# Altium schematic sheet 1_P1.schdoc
size 358 x 218 mm; Symbol: Sheet-Symbol_A4; Device: Sheet-Symbol_A4; @Project Name: 无人机遥控器; @Page Count: 1; @Update Date: 2025-06-11; @Create Date: 2025-01-15; @Schematic Name: Schematic1; @Page No: 1; @Page Name: P1; @Board Name: Board1; Company: 嘉立创EDA; Version: V1.0; Page Size: A4; Convert to PCB: yes; Add into BOM: yes; @Create Time: 08:23:44; @Update Time: 22:29:00; Width: 1377.9527559055118; Height: 825; Region Start: 1; X Region Count: 6; Y Region Count: 4; Blade Width: 10; Title Block Position: 3
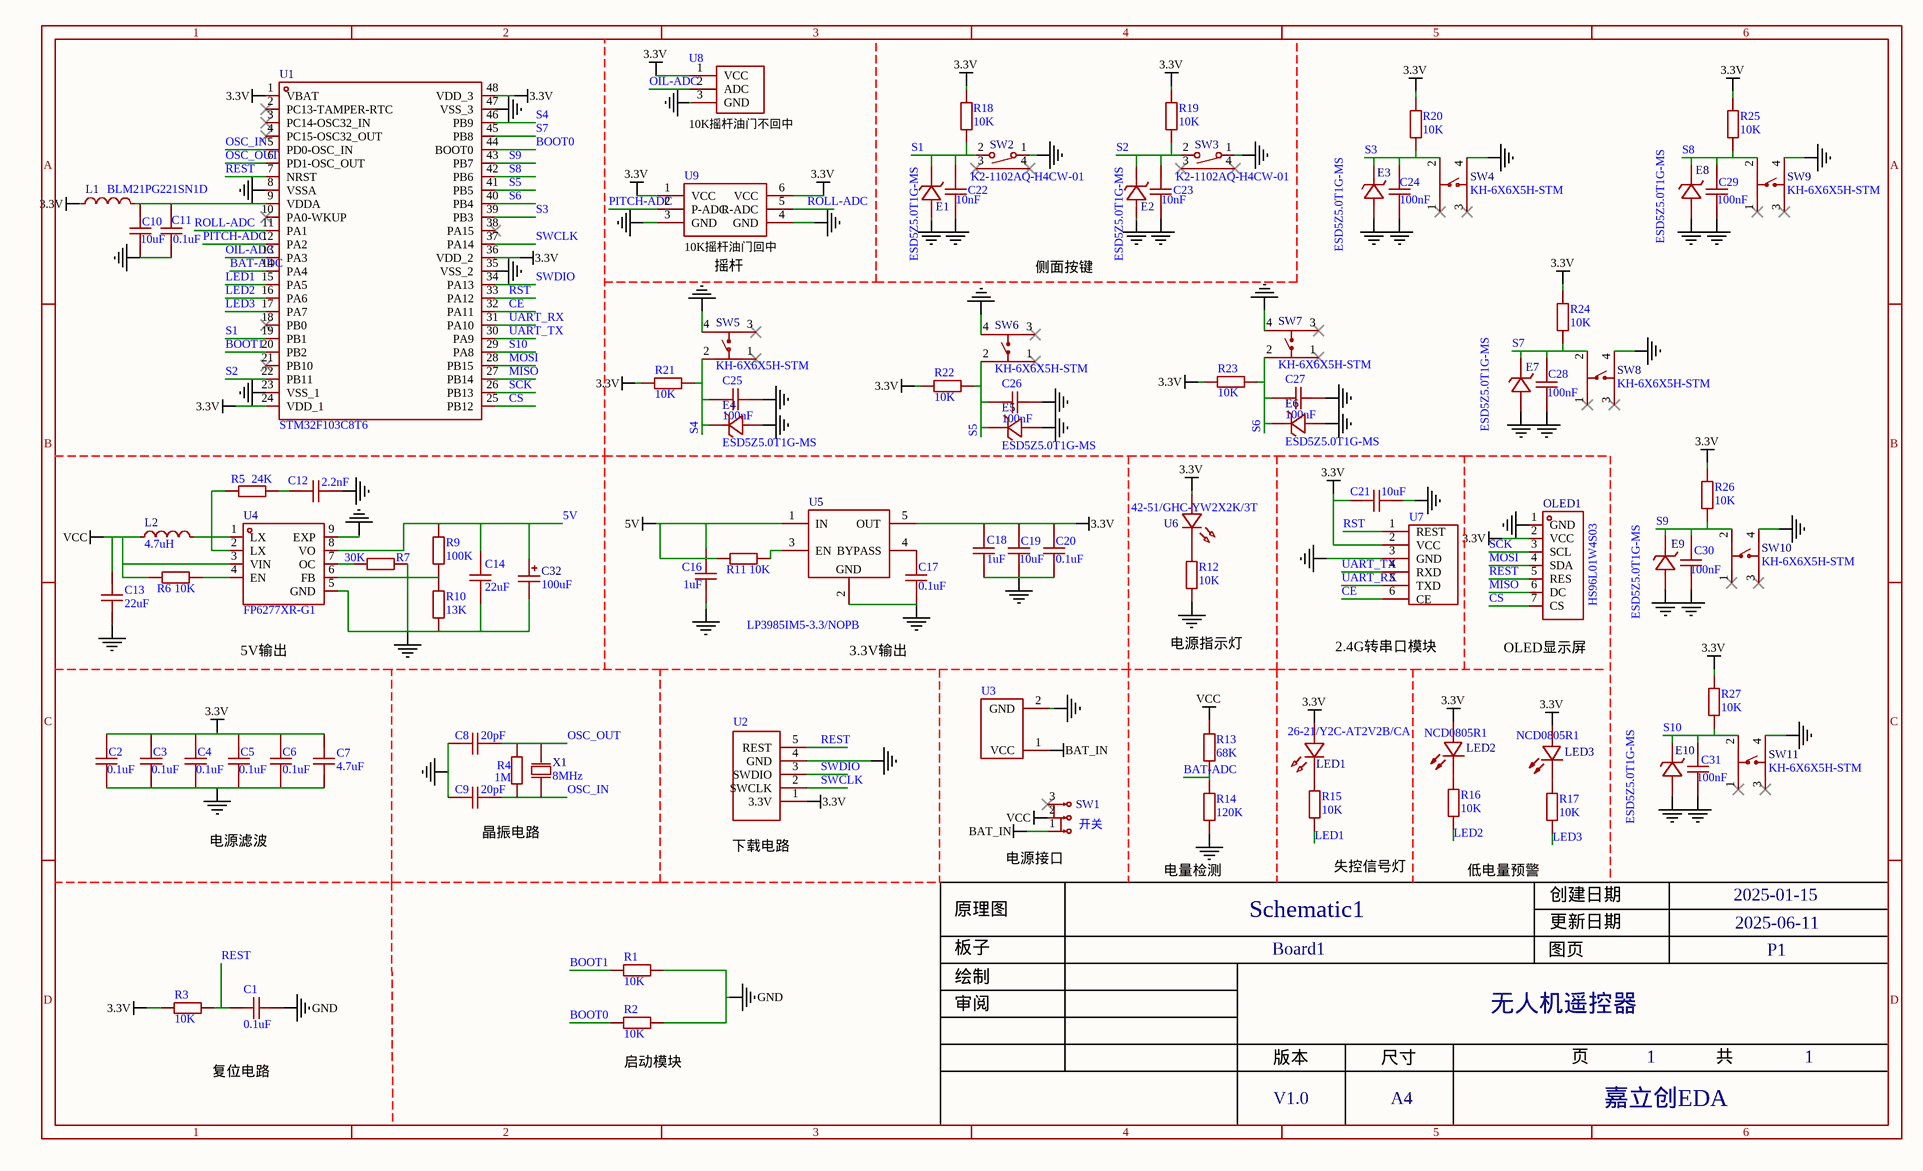
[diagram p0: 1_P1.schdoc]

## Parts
C1  0.1uF  [C0603]
C2  0.1uF  [C0603]
C3  0.1uF  [C0603]
C4  0.1uF  [C0603]
C5  0.1uF  [C0603]
C6  0.1uF  [C0603]
C7  4.7uF  [C0603]
C8  20pF  [C0603]
C9  20pF  [C0603]
C10  10uF  [C0603]
C11  0.1uF  [C0603]
C12  2.2nF  [C0603]
C13  22uF  [C0603]
C14  22uF  [C0603]
C16  1uF  [C0603]
C17  0.1uF  [C0603]
C18  1uF  [C0603]
C19  10uF  [C0603]
C20  0.1uF  [C0603]
C21  10uF  [C0603]
C22  10nF  [C0603]
C23  10nF  [C0603]
C24  100nF  [C0603]
C25  100nF  [C0603]
C26  100nF  [C0603]
C27  100nF  [C0603]
C28  100nF  [C0603]
C29  100nF  [C0603]
C30  100nF  [C0603]
C31  100nF  [C0603]
C32  100uF  [CASE-D_7343]
E1  ESD5Z5.0T1G-MS  [SOD-523_L1.2-W0.8-LS1.6-RD]
E2  ESD5Z5.0T1G-MS  [SOD-523_L1.2-W0.8-LS1.6-RD]
E3  ESD5Z5.0T1G-MS  [SOD-523_L1.2-W0.8-LS1.6-RD]
E4  ESD5Z5.0T1G-MS  [SOD-523_L1.2-W0.8-LS1.6-RD]
E5  ESD5Z5.0T1G-MS  [SOD-523_L1.2-W0.8-LS1.6-RD]
E6  ESD5Z5.0T1G-MS  [SOD-523_L1.2-W0.8-LS1.6-RD]
E7  ESD5Z5.0T1G-MS  [SOD-523_L1.2-W0.8-LS1.6-RD]
E8  ESD5Z5.0T1G-MS  [SOD-523_L1.2-W0.8-LS1.6-RD]
E9  ESD5Z5.0T1G-MS  [SOD-523_L1.2-W0.8-LS1.6-RD]
E10  ESD5Z5.0T1G-MS  [SOD-523_L1.2-W0.8-LS1.6-RD]
L1  BLM21PG221SN1D  [L0805]
L2  4.7uH  [L0603]
LED1  26-21/Y2C-AT2V2B/CA  [LED1206-RD]
LED2  NCD0805R1  [LED0805-R-RD]
LED3  NCD0805R1  [LED0805-R-RD]
OLED1  HS96L01W4S03  [OLED-TH_HS96L01W4S03]
R1  10K  [R0603]
R2  10K  [R0603]
R3  10K  [R0603]
R4  1M  [R0603]
R5  24K  [R0603]
R6  10K  [R0603]
R7  30K  [R0603]
R9  100K  [R0603]
R10  13K  [R0603]
R11  10K  [R0603]
R12  10K  [R0603]
R13  68K  [R0603]
R14  120K  [R0603]
R15  10K  [R0603]
R16  10K  [R0603]
R17  10K  [R0603]
R18  10K  [R0603]
R19  10K  [R0603]
R20  10K  [R0603]
R21  10K  [R0603]
R22  10K  [R0603]
R23  10K  [R0603]
R24  10K  [R0603]
R25  10K  [R0603]
R26  10K  [R0603]
R27  10K  [R0603]
SW1  开关  [SW-TH_SS-12D01-GX]
SW2  K2-1102AQ-H4CW-01  [SW-TH_K2-1102BQ-G4CW-01]
SW3  K2-1102AQ-H4CW-01  [SW-TH_K2-1102BQ-G4CW-01]
SW4  KH-6X6X5H-STM  [SW-SMD_4P-L6.0-W6.0-P4.50-LS9.0-2]
SW5  KH-6X6X5H-STM  [SW-SMD_4P-L6.0-W6.0-P4.50-LS9.0-2]
SW6  KH-6X6X5H-STM  [SW-SMD_4P-L6.0-W6.0-P4.50-LS9.0-2]
SW7  KH-6X6X5H-STM  [SW-SMD_4P-L6.0-W6.0-P4.50-LS9.0-2]
SW8  KH-6X6X5H-STM  [SW-SMD_4P-L6.0-W6.0-P4.50-LS9.0-2]
SW9  KH-6X6X5H-STM  [SW-SMD_4P-L6.0-W6.0-P4.50-LS9.0-2]
SW10  KH-6X6X5H-STM  [SW-SMD_4P-L6.0-W6.0-P4.50-LS9.0-2]
SW11  KH-6X6X5H-STM  [SW-SMD_4P-L6.0-W6.0-P4.50-LS9.0-2]
U1  STM32F103C8T6  [LQFP-48_L7.0-W7.0-P0.50-LS9.0-BL]
U2  (no value)  [stm32f103swd下载口]
U3  (no value)  [电源插座]
U4  FP6277XR-G1  [SOP-8_L4.9-W3.9-P1.27-LS6.0-BL-EP]
U5  LP3985IM5-3.3/NOPB  [SOT-23-5_L3.0-W1.7-P0.95-LS2.8-BR]
U6  42-51/GHC-YW2X2K/3T  [LED-SMD_L1.6-W0.8-FD_GREEN-1]
U7  (no value)  [2.4G转串口]
U8  (no value)  [10K摇杆油门不回中]
U9  (no value)  [10K摇杆油门回中]
X1  8MHz  [OSC-TH_L10.0-W4.5-P5.00]

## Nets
3.3V: C2.2 C3.2 C4.2 C5.2 C6.2 C7.2 C18.2 C19.2 C20.2 C21.1 L1.1 LED1.2(A) LED2.1(+) LED3.1(+) OLED1.2(VCC) R3.1 R18.2 R19.2 R20.2 R21.2 R22.2 R23.2 R24.2 R25.2 R26.2 R27.2 U1.1(VBAT) U1.24(VDD_1) U1.36(VDD_2) U1.48(VDD_3) U2.1(3.3V) U5.5(OUT) U6.1(A) U7.2(VCC) U8.1(VCC) U9.1(VCC) U9.6(VCC)
5V: C14.2 C16.2 C32.1 R9.2 R11.1 U4.8(VO) U5.1(IN)
BAT_IN: SW1.1 U3.1(VCC)
GND: C1.2 C2.1 C3.1 C4.1 C5.1 C6.1 C7.1 C8.1 C9.1 C10.1 C11.1 C12.2 C13.1 C14.1 C16.1 C17.1 C18.1 C19.1 C20.1 C21.2 C22.1 C23.1 C24.1 C25.1 C26.1 C27.1 C28.1 C29.1 C30.1 C31.1 C32.2 E1.2(A) E2.2(A) E3.2(A) E4.2(A) E5.2(A) E6.2(A) E7.2(A) E8.2(A) E9.2(A) E10.2(A) OLED1.1(GND) R1.2 R2.2 R7.2 R10.1 R12.2 R14.1 SW2.1 SW3.1 SW4.4 SW5.4 SW6.4 SW7.4 SW8.4 SW9.4 SW10.4 SW11.4 U1.8(VSSA) U1.23(VSS_1) U1.35(VSS_2) U1.47(VSS_3) U2.4(GND) U3.2(GND) U4.5(GND) U4.9(EXP) U5.2(GND) U7.3(GND) U8.3(GND) U9.3(GND) U9.4(GND)
VCC: C13.2 L2.1 R6.1 R13.2 SW1.2 U4.3(VIN)
BAT-ADC: R13.1 R14.2 U1.14(PA4)
BOOT0: R2.1 U1.44(BOOT0)
BOOT1: R1.1 U1.20(PB2)
CE: U1.32(PA11) U7.6(CE)
CS: OLED1.7(CS) U1.25(PB12)
LED1: R15.1 U1.15(PA5)
LED2: R16.1 U1.16(PA6)
LED3: R17.1 U1.17(PA7)
MISO: OLED1.6(DC) U1.27(PB14)
MOSI: OLED1.4(SDA) U1.28(PB15)
OIL-ADC: U1.13(PA3) U8.2(ADC)
OSC_IN: C9.2 R4.2 U1.5(PD0-OSC_IN) X1.2(OSC2)
OSC_OUT: C8.2 R4.1 U1.6(PD1-OSC_OUT) X1.1(OSC1)
PITCH-ADC: U1.12(PA2) U9.2(P-ADC)
REST: C1.1 OLED1.5(RES) R3.2 U1.7(NRST) U2.5(REST)
ROLL-ADC: U1.11(PA1) U9.5(R-ADC)
RST: U1.33(PA12) U7.1(REST)
S1: C22.2 E1.1(C) R18.1 SW2.2 U1.19(PB1)
S2: C23.2 E2.1(C) R19.1 SW3.2 U1.22(PB11)
S3: C24.2 E3.1(C) R20.1 SW4.2 U1.39(PB3)
S4: C25.2 E4.1(C) R21.1 SW5.2 U1.46(PB9)
S5: C26.2 E5.1(C) R22.1 SW6.2 U1.41(PB5)
S6: C27.2 E6.1(C) R23.1 SW7.2 U1.40(PB4)
S7: C28.2 E7.1(C) R24.1 SW8.2 U1.45(PB8)
S8: C29.2 E8.1(C) R25.1 SW9.2 U1.42(PB6)
S9: C30.2 E9.1(C) R26.1 SW10.2 U1.43(PB7)
S10: C31.2 E10.1(C) R27.1 SW11.2 U1.29(PA8)
SCK: OLED1.3(SCL) U1.26(PB13)
SWCLK: U1.37(PA14) U2.2(SWCLK)
SWDIO: U1.34(PA13) U2.3(SWDIO)
UART_RX: U1.31(PA10) U7.5(TXD)
UART_TX: U1.30(PA9) U7.4(RXD)
NetC10_2: C10.2 C11.2 L1.2 U1.9(VDDA)
NetC12_1: C12.1 R5.2
NetC17_2: C17.2 U5.4(BYPASS)
NetL2_2: L2.2 R5.1 U4.1(LX) U4.2(LX)
NetLED1_1: LED1.1(K) R15.2
NetLED2_2: LED2.2(-) R16.2
NetLED3_2: LED3.2(-) R17.2
NetR6_2: R6.2 U4.4(EN)
NetR7_1: R7.1 U4.7(OC)
NetR9_1: R9.1 R10.2 U4.6(FB)
NetR11_2: R11.2 U5.3(EN)
NetR12_1: R12.1 U6.2(C)

Not connected (* = marked no-connect by the designer): SW1 3*; SW2 3* 4*; SW3 3* 4*; SW4 1* 3*; SW5 1* 3*; SW6 1* 3*; SW7 1* 3*; SW8 1* 3*; SW9 1* 3*; SW10 1* 3*; SW11 1* 3*; U1 2(PC13-TAMPER-RTC)* 3(PC14-OSC32_IN)* 4(PC15-OSC32_OUT)* 10(PA0-WKUP)* 18(PB0)* 21(PB10)* 38(PA15)*

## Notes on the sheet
- 摇杆
- 侧面按键
- (near U4) 5V输出
- 3.3V输出
- (near R12) 电源指示灯
- (near U7) 2.4G转串口模块
- (near OLED1) OLED显示屏
- 电源滤波
- 晶振电路
- (near U2) 下载电路
- (near SW1) 电源接口
- (near R14) 电量检测
- (near R15) 失控信号灯
- 低电量预警
- 复位电路
- (near R2) 启动模块

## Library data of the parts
C1 C3-C14 C16-C31 = CAP_0603: Symbol: CapAcitance; Convert to PCB: yes
C2 = CAP_0603: Symbol: CapAcitance; Convert to PCB: yes; Value: 100nF
C32 = TAJD107K016RNJ: Manufacturer: Kyocera AVX; Add into BOM: yes; Tolerance: ±10%; Rated Voltage: 16V; Equivalent Series Resistance(ESR): 600mΩ@100kHz
E1-E10 = ESD5Z5.0T1G-MS: Manufacturer: MSKSEMI(美森科); Add into BOM: yes; Reverse Stand-Off Voltage (Vrwm): 5V; Maximum Clamping Voltage: 18.6V; Peak Pulse Current (Ipp)@10/1000us: 9.4A; Peak Pulse Power Dissipation (Ppp)@10/1000us: 174W; Breakdown Voltage: 6.2V
L1 = BLM21PG221SN1D: Manufacturer: muRata(村田); Add into BOM: yes; Impedance @ Frequency: 220Ω@100MHz; Tolerance: ±25%; DC Resistance: 45mΩ; Current Rating: 2A; Circuits: 1
L2 = L_0603: Symbol: SDFL1608S100KTF; Add into BOM: yes
LED1 = 26-21/Y2C-AT2V2B/CA: Manufacturer: EVERLIGHT(亿光); Add into BOM: yes; Emitted Color: 黄色; Forward Voltage (VF): 1.75V~2.35V; Dominant Wavelength: 585.5nm~594.5nm; Peak Wavelength: 591nm; Lens Color: 无色透明透镜; Luminous Intensity: 1120mcd
LED2 LED3 = NCD0805R1: Manufacturer: 国星光电; Symbol: FC-2012HRK-620D; Add into BOM: yes; Emitted Color: 红色; Forward Voltage (VF): 1.6V~2.6V; Power Dissipation: 65mW; Forward Current: 20mA; Dominant Wavelength: 615nm~630nm; Diode Configuration: 独立二极管; Lens Color: 无色透明透镜; Luminous Intensity: 67mcd~195mcd; Viewing Angle: 130°
OLED1 = HS96L01W4S03: Manufacturer: HS(汉昇); Add into BOM: yes
R1-R7 R9-R12 R14-R27 = Res_0603: Symbol: 电阻; Convert to PCB: yes
R13 = Res_0603: Symbol: 电阻; Convert to PCB: yes; Value: 10K
SW1 = 开关: Add into BOM: yes
SW2 SW3 = K2-1102AQ-H4CW-01: Manufacturer: 韩国韩荣; Add into BOM: yes; Operating Force: 250gf; Switch Length: 6mm; Switch Height: 7.5mm; Strike Gundam: 带支架; Contact Current: 50mA; Voltage Rating (DC): 12V; Insulation Resistance: 100MΩ; Mechanical Life: 10万次
SW4-SW11 = KH-6X6X5H-STM: Manufacturer: kinghelm(金航标); Add into BOM: yes; Circuit: 单刀单掷; Actuator Style: 圆形按钮; Switch Length: 6mm; Switch Height: 5mm; Strike Gundam: 不带; Contact Current: 50mA; Voltage Rating (DC): 12V; Actuator/Cap Color: 黑色; Pin Style: 鸥翼型; Mechanical Life: 8万次
U1 = STM32F103C8T6: Manufacturer: ST(意法半导体); Add into BOM: yes; CPU Core: ARM Cortex-M3; Maximum Frequency: 72MHz; Supply Voltage Range: 2V~3.6V; Internal Oscillator: 有; Program FLASH Size: 64K@x8bit; RAM Size: 20KB; GPIO Ports Number: 37; ADC (Units/Channels/bits): 1@x10ch/12bit; Peripherals / Functions / Protocol Stacks: 温度传感器；DMA；看门狗；POR；PWM
U2 = stm32f103下载口: Add into BOM: yes
U3 = 电源插座: Add into BOM: yes
U4 = FP6277XR-G1: Manufacturer: Feeling Technology(台湾远翔); Add into BOM: yes; Function: 升压型; Synchronous Rectification: 是; Number of Outputs: 1; Topology: 升压式; Input Voltage: 2.4V~4.5V; Output Voltage: 5.3V; Switching Frequency: 500kHz
U5 = LP3985IM5-3.3/NOPB: Manufacturer: TI(德州仪器); Add into BOM: yes; Output Type: 固定; Maximum Input Voltage: 6V; Output Voltage: 3.3V; MAX Output Current: 150mA; Power Supply Rejection Ratio (PSRR): 50dB; Dropout Voltage: 100mV@(150mA); standby current: 150uA; Output Polarity: 正极; Number of Outputs: 1
U6 = 42-51/GHC-YW2X2K/3T: Manufacturer: EVERLIGHT(亿光); Add into BOM: yes; Emitted Color: 翠绿色; Dominant Wavelength: 520nm~535nm; Luminous Intensity: 2850mcd
U7 = 2.4G转串口: Add into BOM: yes
U8 = 10K摇杆油门不回中: Add into BOM: yes
U9 = 10K摇杆油门回中: Add into BOM: yes
X1 = X49SD8MSD2SC: Manufacturer: YXC(扬兴晶振); Add into BOM: yes; Crystal Type: 直插晶振; Normal temperature Frequency Tolerance: ±20ppm; External load capacitor: 20pF; Frequency Stability(Full temperature range): ±30ppm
